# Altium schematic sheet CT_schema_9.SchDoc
size 254 x 194 mm
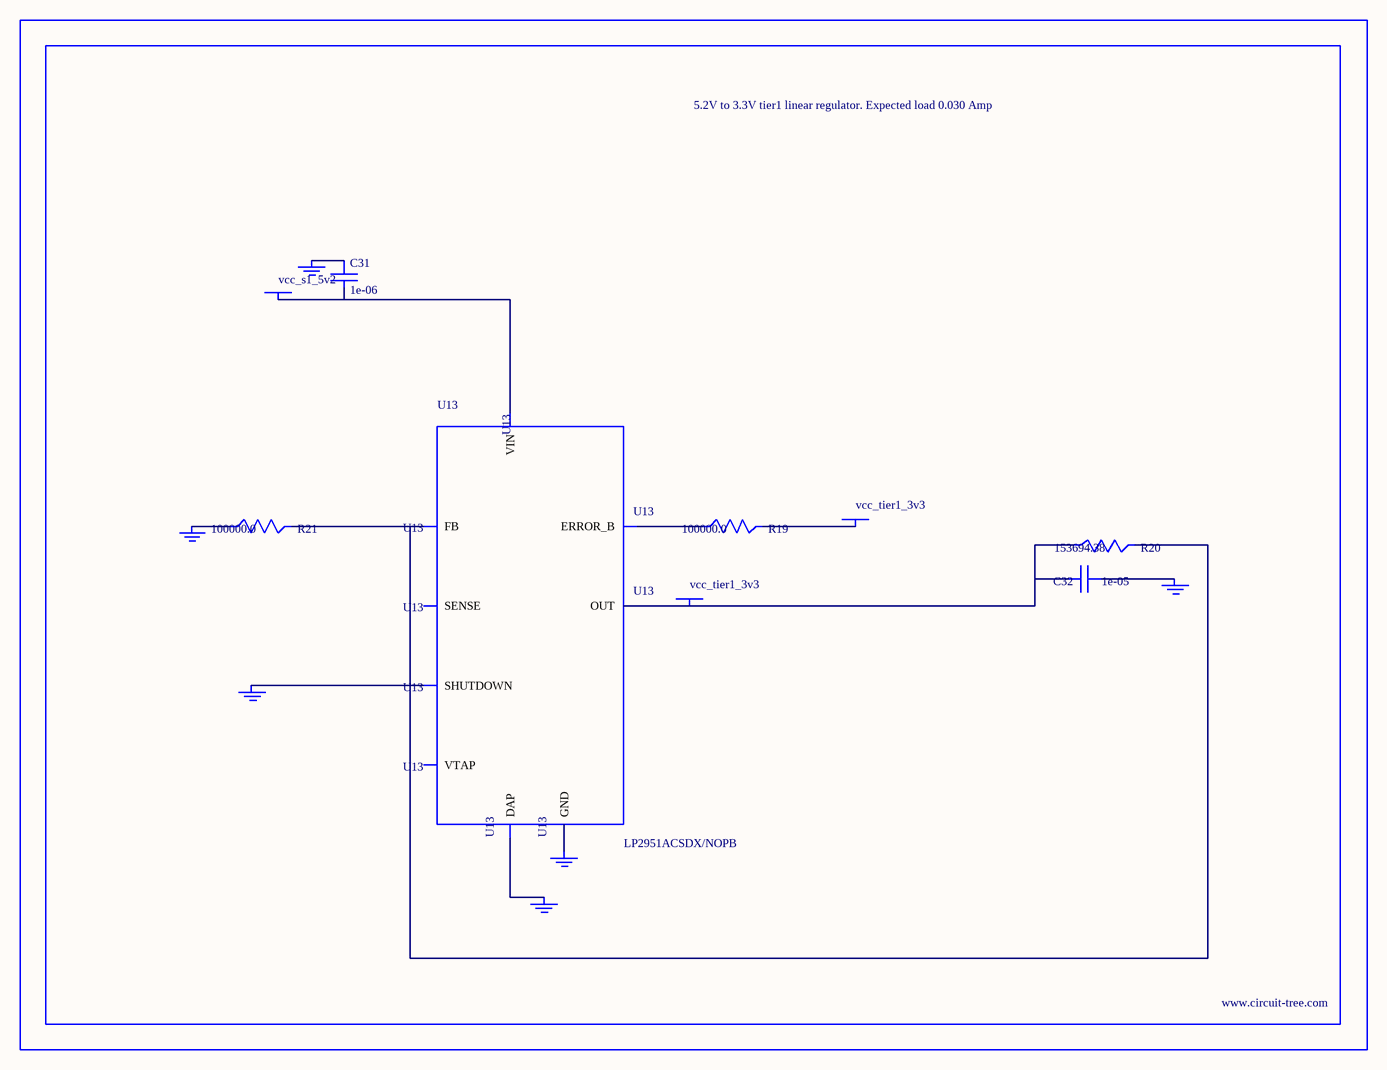
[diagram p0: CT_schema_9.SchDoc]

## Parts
BORDER8  (no value)
C31  1e-06  [C0603]
C32  1e-05  [C1210]
GND_INSTANCE_8_0  (no value)
GND_INSTANCE_8_1  (no value)
GND_INSTANCE_8_2  (no value)
GND_INSTANCE_8_3  (no value)
GND_INSTANCE_8_4  (no value)
GND_INSTANCE_8_5  (no value)
POWER_INSTANCE_8_0  vcc_tier1_3v3
POWER_INSTANCE_8_1  vcc_s1_5v2
POWER_INSTANCE_8_2  vcc_tier1_3v3
R19  100000.0  [R0603]
R20  153694.38  [R0603]
R21  100000.0  [R0603]
U13  LP2951ACSDX/NOPB  [WSON-8]

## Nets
NetC31_1: C31.1 GND_INSTANCE_8_3.0(GND)
NetC31_2: C31.2 POWER_INSTANCE_8_1.0(PWR) U13.8(VIN)
NetC32_1: C32.1 GND_INSTANCE_8_0.0(GND)
NetC32_2: C32.2 POWER_INSTANCE_8_2.0(PWR) R20.1 U13.1(OUT)
NetGND_INSTANCE_8_1_0: GND_INSTANCE_8_1.0(GND) U13.3(SHUTDOWN)
NetGND_INSTANCE_8_2_0: GND_INSTANCE_8_2.0(GND) R21.1
NetGND_INSTANCE_8_4_0: GND_INSTANCE_8_4.0(GND) U13.PAD(DAP)
NetGND_INSTANCE_8_5_0: GND_INSTANCE_8_5.0(GND) U13.4(GND)
NetPOWER_INSTANCE_8_0_0: POWER_INSTANCE_8_0.0(PWR) R19.2
NetR19_1: R19.1 U13.5(ERROR_B)
NetR20_2: R20.2 R21.2 U13.7(FB)

Not connected (* = marked no-connect by the designer): U13 2(SENSE) 6(VTAP)

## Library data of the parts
BORDER8 = BORDER_PAGE8
C31 = C0603C105K3RACTU
C32 = GRM32DR61E106MA12L
GND_INSTANCE_8_0-GND_INSTANCE_8_5 = GND
POWER_INSTANCE_8_0-POWER_INSTANCE_8_2 = PWR
R19 R21 = RC0603JR-07100KL
R20 = R20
